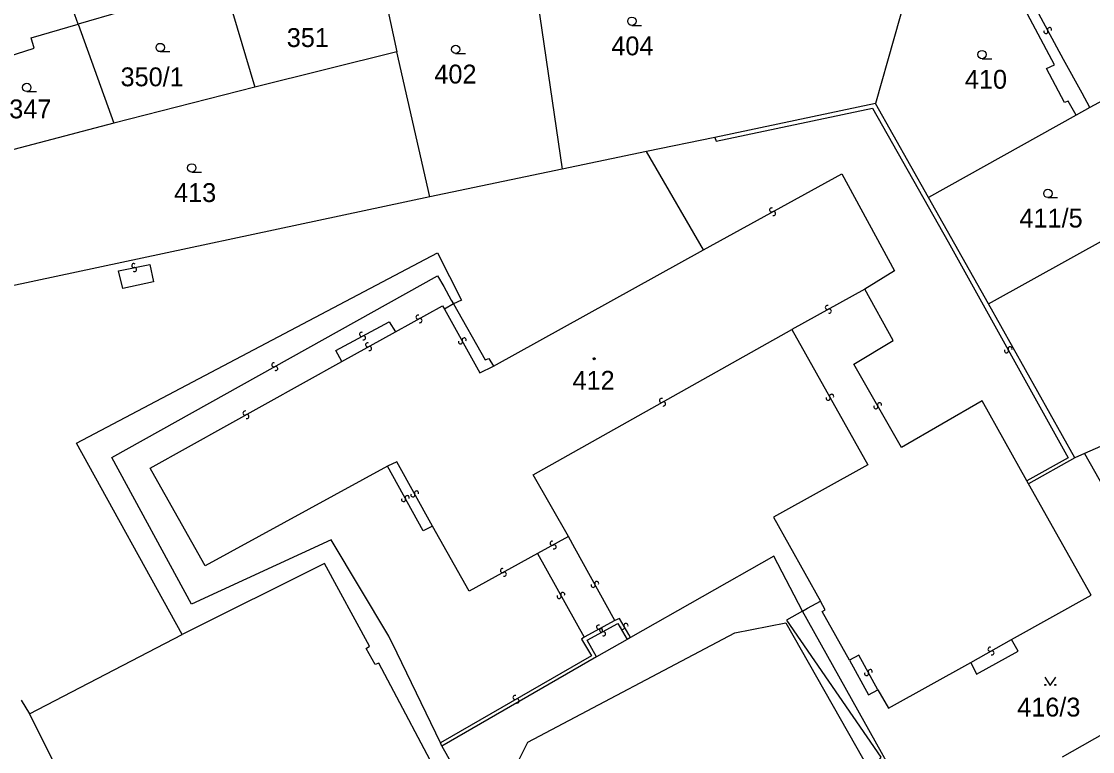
# Model space of a CAD drawing. Extents: x -600391 to -599491, y -1160176 to -1159402.
# Drawn here: x -600153 to -600056.6, y -1159726.9 to -1159661.1 of the extents above; entities that cross this region are included whole.
import ezdxf

# ---------------------------------------------------------------- set-up
doc = ezdxf.new("R2010")
doc.units = 0
for name, color, linetype in [('Level 1', 7, 'Continuous'), ('Level 13', 7, 'Continuous'), ('Level 3', 7, 'Continuous'), ('Level 4', 7, 'Continuous'), ('Level 5', 7, 'Continuous')]:
    doc.layers.add(name, color=color, linetype=linetype)

msp = doc.modelspace()

# ---------------------------------------------------------------- linework, layer by layer
at = {"layer": 'Level 1'}
for points in [[(-600109.98, -1159635.79), (-600104.36, -1159674.43)], [(-600139.22, -1159642.8), (-600132.03, -1159667.05)], [(-600147.93, -1159661.35), (-600148.98, -1159658.4), (-600149.65, -1159656.72), (-600151.5, -1159651.28)], [(-600121.38, -1159653.93), (-600119.22, -1159663.85)], [(-600058.07, -1159669.57), (-600058.78, -1159668.3), (-600059.12, -1159668.41), (-600060.74, -1159665.36), (-600060, -1159665.02), (-600063.19, -1159659.02), (-600057.4, -1159655.73)], [(-600072.82, -1159656.83), (-600076.12, -1159668.51)], [(-600140.07, -1159659.06), (-600147.93, -1159661.35)], [(-600157.55, -1159665.32), (-600151.9, -1159663.52), (-600152.17, -1159662.59), (-600147.93, -1159661.35)], [(-600147.93, -1159661.35), (-600144.73, -1159670.29)], [(-600119.22, -1159663.85), (-600132.03, -1159667.05)], [(-600116.25, -1159676.91), (-600119.22, -1159663.85)], [(-600132.03, -1159667.05), (-600144.73, -1159670.29)], [(-600055.28, -1159668.04), (-600056.83, -1159668.88)], [(-600076.12, -1159668.51), (-600090.59, -1159671.58)], [(-600071.36, -1159676.97), (-600076.12, -1159668.51)], [(-600056.83, -1159668.88), (-600058.07, -1159669.57)], [(-600058.07, -1159669.57), (-600071.36, -1159676.97)], [(-600144.73, -1159670.29), (-600158.77, -1159673.99)], [(-600090.59, -1159671.58), (-600096.74, -1159672.83)], [(-600096.74, -1159672.83), (-600104.36, -1159674.43)], [(-600091.62, -1159681.69), (-600096.74, -1159672.83)], [(-600104.36, -1159674.43), (-600116.25, -1159676.91)], [(-600116.25, -1159676.91), (-600153.99, -1159684.97)], [(-600065.97, -1159686.56), (-600071.36, -1159676.97)], [(-600065.97, -1159686.56), (-600051.39, -1159678.5)], [(-600138.57, -1159716.38), (-600148.09, -1159699.12), (-600115.57, -1159681.96), (-600113.41, -1159686.25), (-600114.12, -1159686.57)], [(-600110.54, -1159692.17), (-600091.62, -1159681.69)], [(-600114.12, -1159686.57), (-600111.29, -1159691.62), (-600110.94, -1159691.49), (-600110.54, -1159692.17)], [(-600058.19, -1159700.44), (-600065.97, -1159686.56)], [(-600046.49, -1159695.3), (-600057.31, -1159700.06)], [(-600058.19, -1159700.44), (-600062.34, -1159702.78)], [(-600057.31, -1159700.06), (-600046.1, -1159719.91), (-600059.31, -1159727.41)], [(-600057.31, -1159700.06), (-600058.19, -1159700.44)], [(-600063.89, -1159716.82), (-600056.72, -1159712.82), (-600062.34, -1159702.78)], [(-600082.71, -1159714.26), (-600085.3, -1159709.31), (-600098.18, -1159716.64)], [(-600082.71, -1159714.26), (-600082.25, -1159714), (-600081.09, -1159713.35)], [(-600078.48, -1159718.68), (-600080.92, -1159714.29), (-600080.65, -1159714.14), (-600081.09, -1159713.35)], [(-600082.71, -1159714.26), (-600084.16, -1159715.08), (-600075.64, -1159727.42), (-600076.56, -1159728.8)], [(-600080.88, -1159739.19), (-600071.59, -1159734.15), (-600082.71, -1159714.26)], [(-600152.3, -1159723.51), (-600138.57, -1159716.38)], [(-600098.48, -1159716.81), (-600101.25, -1159718.39)], [(-600098.18, -1159716.64), (-600098.48, -1159716.81)], [(-600067.56, -1159718.89), (-600067.05, -1159719.95), (-600063.27, -1159717.86), (-600063.89, -1159716.82)], [(-600101.25, -1159718.39), (-600115.17, -1159726.43)], [(-600078.48, -1159718.68), (-600076.75, -1159721.81), (-600075.92, -1159721.35)], [(-600075.92, -1159721.35), (-600074.97, -1159723.02), (-600067.56, -1159718.89)], [(-600153.05, -1159722.28), (-600152.3, -1159723.51)], [(-600152.3, -1159723.51), (-600146.3, -1159735.55)], [(-600115.17, -1159726.43), (-600112.68, -1159730.81)]]:
    msp.add_lwpolyline(points, dxfattribs=at)
at = {"layer": 'Level 13'}
for centre, start, end in [((-600060.783, -1159662.026), 155.79794, 27.89594), ((-600060.458, -1159661.853), 335.58349, 208.17349), ((-600085.487, -1159678.108), 66.19236, 298.29036), ((-600085.312, -1159678.432), 245.9779, 118.5679), ((-600142.925, -1159683.119), 48.72146, 280.81946), ((-600142.855, -1159683.481), 228.507, 101.097), ((-600080.469, -1159686.899), 66.27948, 298.86948), ((-600080.292, -1159687.222), 246.49393, 118.59193), ((-600117.328, -1159687.758), 66.26646, 298.36446), ((-600117.152, -1159688.082), 246.052, 118.642), ((-600122.406, -1159689.317), 65.67349, 297.77149), ((-600122.233, -1159689.642), 245.45903, 118.04903), ((-600121.868, -1159690.268), 66.39711, 298.49511), ((-600113.501, -1159689.999), 156.22989, 28.81989), ((-600113.178, -1159689.822), 336.44434, 208.54234), ((-600121.691, -1159690.591), 246.18266, 118.77266), ((-600064.341, -1159690.799), 156.24539, 28.83539), ((-600064.018, -1159690.622), 336.45984, 208.55784), ((-600130.318, -1159692.068), 66.55489, 298.65289), ((-600130.141, -1159692.391), 246.34044, 118.93044), ((-600095.399, -1159695.268), 66.68143, 298.77943), ((-600080.401, -1159695.079), 156.4357, 29.0257), ((-600080.078, -1159694.901), 336.65015, 208.74815), ((-600095.221, -1159695.591), 246.46697, 119.05697), ((-600076.091, -1159695.84), 157.04381, 29.14181), ((-600075.77, -1159695.66), 336.82936, 209.41936), ((-600132.908, -1159696.408), 66.46962, 298.56762), ((-600132.731, -1159696.731), 246.25517, 118.84517), ((-600117.782, -1159703.788), 156.49463, 28.59262), ((-600117.459, -1159703.611), 336.28017, 208.87017), ((-600118.622, -1159704.208), 156.28529, 28.38329), ((-600118.298, -1159704.032), 336.07083, 208.66083), ((-600105.248, -1159708.148), 66.05572, 298.64572), ((-600105.072, -1159708.472), 246.27017, 118.36817), ((-600109.728, -1159710.608), 65.98335, 298.57335), ((-600109.553, -1159710.932), 246.19781, 118.29581), ((-600101.562, -1159711.937), 156.17342, 28.27142), ((-600101.238, -1159711.762), 335.95897, 208.54897), ((-600104.621, -1159712.939), 156.3097, 28.8997), ((-600104.298, -1159712.762), 336.52415, 208.62215), ((-600098.601, -1159715.547), 337.58879, 210.17879), ((-600101.067, -1159715.698), 65.76874, 298.35874), ((-600100.796, -1159715.977), 65.56276, 297.66076), ((-600100.893, -1159716.023), 245.98319, 118.08119), ((-600100.624, -1159716.303), 245.34831, 117.93831), ((-600098.92, -1159715.732), 157.80325, 29.90124), ((-600065.819, -1159717.699), 66.79715, 298.89515), ((-600065.64, -1159718.021), 246.5827, 119.1727), ((-600076.933, -1159719.887), 156.0348, 28.1328), ((-600076.608, -1159719.712), 335.82034, 208.41034), ((-600108.591, -1159722.04), 67.12531, 299.71531), ((-600108.409, -1159722.361), 247.33976, 119.43776)]:
    msp.add_arc(centre, 0.184, start, end, dxfattribs=at)
at = {"layer": 'Level 3'}
for points in [[(-600056.83, -1159668.88), (-600057.52, -1159667.58), (-600059.21, -1159664.54), (-600062.03, -1159659.33), (-600056.97, -1159656.46)], [(-600090.59, -1159671.58), (-600090.49, -1159671.9), (-600076.41, -1159668.93), (-600069.59, -1159680.99), (-600058.77, -1159700.44), (-600062.49, -1159702.51)], [(-600091.62, -1159681.69), (-600079.17, -1159674.84), (-600074.42, -1159683.6), (-600077.09, -1159685.23)], [(-600143.91, -1159685.17), (-600144.31, -1159683.58), (-600141.47, -1159683.01), (-600141.14, -1159684.59), (-600143.91, -1159685.17)], [(-600115.29, -1159726.12), (-600119.2, -1159718.05), (-600119.97, -1159716.52), (-600125.16, -1159707.85), (-600137.72, -1159713.62), (-600144.89, -1159700.42), (-600115.56, -1159684.04), (-600115, -1159684.99), (-600114.33, -1159686.25), (-600114.12, -1159686.57)], [(-600077.09, -1159685.23), (-600083.66, -1159688.89)], [(-600062.49, -1159702.51), (-600066.52, -1159695.3), (-600073.78, -1159699.52), (-600078.07, -1159691.99), (-600074.53, -1159689.87), (-600077.09, -1159685.23)], [(-600119.36, -1159689.09), (-600115.12, -1159686.75), (-600114.93, -1159687.05)], [(-600114.12, -1159686.57), (-600114.93, -1159687.05)], [(-600114.93, -1159687.05), (-600111.75, -1159692.77), (-600110.54, -1159692.17)], [(-600124.19, -1159691.77), (-600124.73, -1159690.77), (-600119.92, -1159688.18), (-600119.36, -1159689.09)], [(-600124.19, -1159691.77), (-600119.36, -1159689.09)], [(-600103.77, -1159707.54), (-600106.96, -1159701.97), (-600083.66, -1159688.89)], [(-600083.66, -1159688.89), (-600076.82, -1159701.09), (-600085.33, -1159705.79), (-600081.09, -1159713.35)], [(-600120.07, -1159701.2), (-600136.5, -1159710.18), (-600141.29, -1159701.65), (-600141.44, -1159701.37), (-600124.19, -1159691.77)], [(-600116.01, -1159706.59), (-600119.23, -1159700.81), (-600120.07, -1159701.2)], [(-600116.01, -1159706.59), (-600116.85, -1159707.03), (-600120.07, -1159701.2)], [(-600062.34, -1159702.78), (-600062.49, -1159702.51)], [(-600106.56, -1159709.08), (-600112.72, -1159712.47), (-600116.01, -1159706.59)], [(-600103.77, -1159707.54), (-600106.56, -1159709.08)], [(-600099.61, -1159715.11), (-600103.2, -1159708.58), (-600103.77, -1159707.54)], [(-600106.56, -1159709.08), (-600102.36, -1159716.61)], [(-600141.1, -1159745), (-600114.87, -1159730.26), (-600120.86, -1159718.96), (-600121.19, -1159719.08), (-600122.01, -1159717.64), (-600121.69, -1159717.43), (-600125.74, -1159709.97), (-600138.57, -1159716.38)], [(-600109.01, -1159729.18), (-600107.43, -1159726.08), (-600088.79, -1159716.22), (-600084.21, -1159715.32), (-600076.56, -1159728.8)], [(-600099.61, -1159715.11), (-600102.36, -1159716.61)], [(-600098.18, -1159716.64), (-600098.34, -1159716.36), (-600099.18, -1159714.93), (-600099.61, -1159715.11)], [(-600101.25, -1159718.39), (-600102.1, -1159716.88), (-600099.32, -1159715.39), (-600098.48, -1159716.81)], [(-600102.36, -1159716.61), (-600102.61, -1159716.8), (-600101.71, -1159718.29), (-600115.29, -1159726.12)], [(-600067.56, -1159718.89), (-600063.89, -1159716.82)], [(-600075.92, -1159721.35), (-600077.62, -1159718.24), (-600078.48, -1159718.68)], [(-600115.17, -1159726.43), (-600115.29, -1159726.12)]]:
    msp.add_lwpolyline(points, dxfattribs=at)
at = {"layer": 'Level 5'}
for p, q in [((-600098.07, -1159661.47), (-600097.195, -1159661.47)), ((-600140.54, -1159663.84), (-600139.665, -1159663.84)), ((-600113.94, -1159664.01), (-600113.065, -1159664.01)), ((-600066.54, -1159664.48), (-600065.665, -1159664.48)), ((-600152.56, -1159667.44), (-600151.685, -1159667.44)), ((-600137.7, -1159674.69), (-600136.825, -1159674.69)), ((-600060.61, -1159676.99), (-600059.735, -1159676.99))]:
    msp.add_line(p, q, dxfattribs=at)
msp.add_lwpolyline([(-600060.891, -1159720.21), (-600060.39, -1159720.96), (-600059.89, -1159720.21)], dxfattribs=at)
for centre, radius in [((-600098.07, -1159661.095), 0.375), ((-600140.54, -1159663.465), 0.375), ((-600113.94, -1159663.635), 0.375), ((-600066.54, -1159664.105), 0.375), ((-600152.56, -1159667.065), 0.375), ((-600137.7, -1159674.315), 0.375), ((-600060.61, -1159676.615), 0.375), ((-600101.47, -1159691.51), 0.09), ((-600101.47, -1159691.51), 0.0521), ((-600060.84, -1159720.91), 0.05), ((-600059.941, -1159720.91), 0.05)]:
    msp.add_circle(centre, radius, dxfattribs=at)

# ---------------------------------------------------------------- texts
at = {"layer": 'Level 4'}
for s, p in [('351', (-600129.145, -1159663.42)), ('404', (-600099.918, -1159664.17)), ('350/1', (-600144.114, -1159666.96)), ('402', (-600115.853, -1159666.71)), ('410', (-600068.081, -1159667.18)), ('347', (-600154.136, -1159669.85)), ('413', (-600139.294, -1159677.39)), ('411/5', (-600063.166, -1159679.69)), ('412', (-600103.412, -1159694.31)), ('416/3', (-600063.369, -1159723.76))]:
    msp.add_text(s, height=1.7, dxfattribs=at).set_placement(p)

doc.saveas('drawing.dxf')
